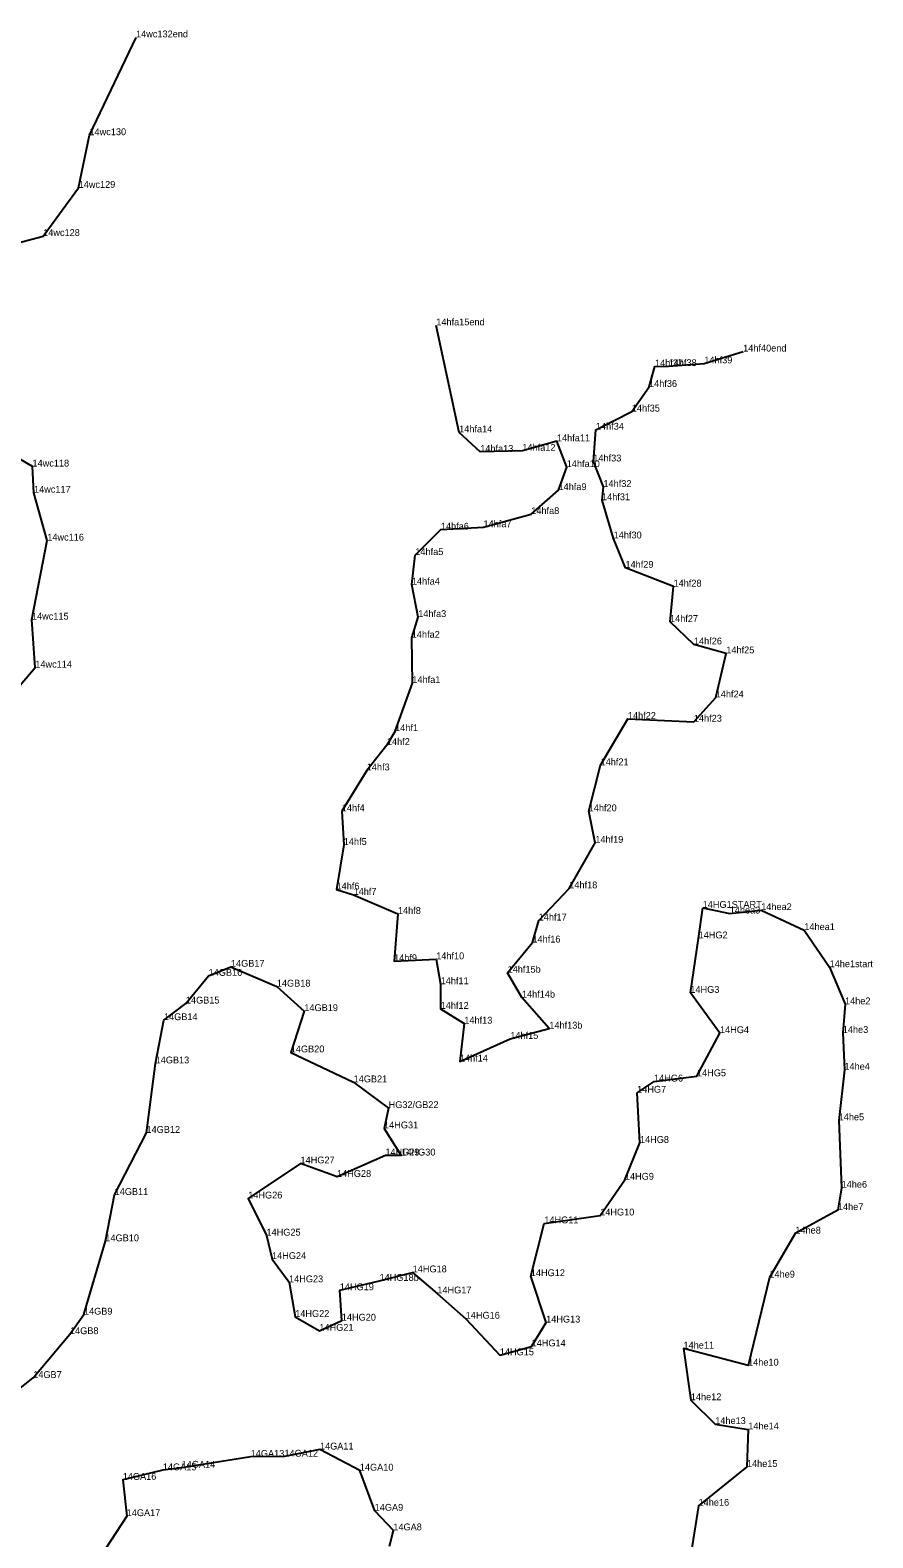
# Model space of a CAD drawing. Extents: x 2072529 to 2267990, y 436423 to 470008.
# Drawn here: x 2256512 to 2257127, y 441770 to 442872 of the extents above; entities that cross this region are included whole.
import ezdxf

# ---------------------------------------------------------------- set-up
doc = ezdxf.new("R2010")
doc.units = 0
doc.layers.add('Level 3', color=7, linetype='Continuous')
doc.layers.add('Old_Level_52', color=7, linetype='Continuous')

msp = doc.modelspace()

# ---------------------------------------------------------------- linework, layer by layer
at = {"layer": 'Level 3'}
for p, q in [((2256588.861, 442866.33), (2256588.861, 442866.33)), ((2256554.839, 442794.87), (2256554.839, 442794.87)), ((2256546.961, 442756.391), (2256546.961, 442756.391)), ((2256521.047, 442721.188), (2256521.047, 442721.188)), ((2256808.072, 442655.895), (2256808.072, 442655.895)), ((2257032.164, 442636.791), (2257032.164, 442636.791)), ((2256967.768, 442625.957), (2256967.768, 442625.957)), ((2256977.718, 442626.158), (2256977.718, 442626.158)), ((2257003.79, 442628.145), (2257003.79, 442628.145)), ((2256963.408, 442610.898), (2256963.408, 442610.898)), ((2256950.871, 442592.936), (2256950.871, 442592.936)), ((2256924.614, 442579.689), (2256924.614, 442579.689)), ((2256824.774, 442577.743), (2256824.774, 442577.743)), ((2256896.18, 442571.22), (2256896.18, 442571.22)), ((2256840.149, 442563.48), (2256840.149, 442563.48)), ((2256870.943, 442564.249), (2256870.943, 442564.249)), ((2256922.747, 442556.483), (2256922.747, 442556.483)), ((2256513.243, 442552.763), (2256513.243, 442552.763)), ((2256903.329, 442552.366), (2256903.329, 442552.366)), ((2256897.343, 442535.552), (2256897.343, 442535.552)), ((2256930.128, 442537.824), (2256930.128, 442537.824)), ((2256514.351, 442533.633), (2256514.351, 442533.633)), ((2256929.089, 442528.143), (2256929.089, 442528.143)), ((2256877.431, 442518.043), (2256877.431, 442518.043)), ((2256811.443, 442506.657), (2256811.443, 442506.657)), ((2256842.568, 442508.441), (2256842.568, 442508.441)), ((2256524.048, 442498.667), (2256524.048, 442498.667)), ((2256937.584, 442500.25), (2256937.584, 442500.25)), ((2256792.765, 442488.079), (2256792.765, 442488.079)), ((2256946.219, 442478.778), (2256946.219, 442478.778)), ((2256790.248, 442466.484), (2256790.248, 442466.484)), ((2256981.308, 442465.031), (2256981.308, 442465.031)), ((2256512.841, 442440.902), (2256512.841, 442440.902)), ((2256794.901, 442442.777), (2256794.901, 442442.777)), ((2256978.733, 442439.22), (2256978.733, 442439.22)), ((2256790.185, 442427.622), (2256790.185, 442427.622)), ((2256996.178, 442422.789), (2256996.178, 442422.789)), ((2257019.843, 442416.274), (2257019.843, 442416.274)), ((2256515.322, 442405.862), (2256515.322, 442405.862)), ((2256790.622, 442394.6), (2256790.622, 442394.6)), ((2257012.095, 442384.028), (2257012.095, 442384.028)), ((2256778.024, 442359.444), (2256778.024, 442359.444)), ((2256947.98, 442368.36), (2256947.98, 442368.36)), ((2256996.142, 442366.341), (2256996.142, 442366.341)), ((2256772.008, 442349.301), (2256772.008, 442349.301)), ((2256757.327, 442330.735), (2256757.327, 442330.735)), ((2256928.051, 442334.516), (2256928.051, 442334.516)), ((2256739.105, 442300.891), (2256739.105, 442300.891)), ((2256919.352, 442300.888), (2256919.352, 442300.888)), ((2256740.524, 442276.298), (2256740.524, 442276.298)), ((2256924.197, 442277.869), (2256924.197, 442277.869)), ((2256735.261, 442243.745), (2256735.261, 442243.745)), ((2256747.704, 442239.841), (2256747.704, 442239.841)), ((2256905.181, 442244.57), (2256905.181, 442244.57)), ((2256780.07, 442225.88), (2256780.07, 442225.88)), ((2257002.603, 442230.336), (2257002.603, 442230.336)), ((2257022.343, 442226.219), (2257022.343, 442226.219)), ((2257045.316, 442228.688), (2257045.316, 442228.688)), ((2256882.843, 442221.092), (2256882.843, 442221.092)), ((2256878.273, 442205), (2256878.273, 442205)), ((2256999.626, 442208.027), (2256999.626, 442208.027)), ((2257076.791, 442214.063), (2257076.791, 442214.063)), ((2256808.014, 442192.769), (2256808.014, 442192.769)), ((2256658.15, 442187.299), (2256658.15, 442187.299)), ((2256777.268, 442191.342), (2256777.268, 442191.342)), ((2256860.153, 442182.951), (2256860.153, 442182.951)), ((2257095.268, 442186.95), (2257095.268, 442186.95)), ((2256641.846, 442180.672), (2256641.846, 442180.672)), ((2256691.652, 442172.807), (2256691.652, 442172.807)), ((2256811.25, 442174.563), (2256811.25, 442174.563)), ((2256625.255, 442160.408), (2256625.255, 442160.408)), ((2256870.613, 442164.726), (2256870.613, 442164.726)), ((2256993.598, 442168.239), (2256993.598, 442168.239)), ((2257106.498, 442159.852), (2257106.498, 442159.852)), ((2256711.722, 442154.914), (2256711.722, 442154.914)), ((2256811.254, 442156.555), (2256811.254, 442156.555)), ((2256609.256, 442148.287), (2256609.256, 442148.287)), ((2256828.537, 442145.732), (2256828.537, 442145.732)), ((2256890.612, 442142.069), (2256890.612, 442142.069)), ((2257015.216, 442138.82), (2257015.216, 442138.82)), ((2257104.886, 442138.965), (2257104.886, 442138.965)), ((2256862.129, 442134.591), (2256862.129, 442134.591)), ((2256603.163, 442116.704), (2256603.163, 442116.704)), ((2256701.831, 442124.753), (2256701.831, 442124.753)), ((2256825.326, 442118.046), (2256825.326, 442118.046)), ((2256998.412, 442107.303), (2256998.412, 442107.303)), ((2257106.071, 442112.024), (2257106.071, 442112.024)), ((2256747.7, 442102.866), (2256747.7, 442102.866)), ((2256954.737, 442095.278), (2256954.737, 442095.278)), ((2256967.057, 442103.445), (2256967.057, 442103.445)), ((2256773.27, 442084.037), (2256773.27, 442084.037)), ((2257101.891, 442075.091), (2257101.891, 442075.091)), ((2256596.481, 442065.935), (2256596.481, 442065.935)), ((2256769.933, 442069.212), (2256769.933, 442069.212)), ((2256956.773, 442058.592), (2256956.773, 442058.592)), ((2256708.948, 442043.636), (2256708.948, 442043.636)), ((2256770.931, 442049.474), (2256770.931, 442049.474)), ((2256782.535, 442049.383), (2256782.535, 442049.383)), ((2256735.603, 442033.763), (2256735.603, 442033.763)), ((2256945.787, 442031.698), (2256945.787, 442031.698)), ((2256573.197, 442020.555), (2256573.197, 442020.555)), ((2256670.785, 442017.999), (2256670.785, 442017.999)), ((2257103.998, 442025.846), (2257103.998, 442025.846)), ((2256927.77, 442005.578), (2256927.77, 442005.578)), ((2257101.305, 442009.514), (2257101.305, 442009.514)), ((2256886.966, 441999.838), (2256886.966, 441999.838)), ((2256566.463, 441986.742), (2256566.463, 441986.742)), ((2256684.098, 441990.857), (2256684.098, 441990.857)), ((2257070.234, 441992.338), (2257070.234, 441992.338)), ((2256688.147, 441973.748), (2256688.147, 441973.748)), ((2256790.82, 441964.029), (2256790.82, 441964.029)), ((2256700.578, 441956.769), (2256700.578, 441956.769)), ((2256737.593, 441950.967), (2256737.593, 441950.967)), ((2256766.648, 441957.788), (2256766.648, 441957.788)), ((2256877.1, 441961.24), (2256877.1, 441961.24)), ((2257051.284, 441960.175), (2257051.284, 441960.175)), ((2256808.839, 441948.627), (2256808.839, 441948.627)), ((2256550.815, 441933.129), (2256550.815, 441933.129)), ((2256705.081, 441931.45), (2256705.081, 441931.45)), ((2256739.1, 441928.741), (2256739.1, 441928.741)), ((2256829.569, 441930.176), (2256829.569, 441930.176)), ((2256540.62, 441918.878), (2256540.62, 441918.878)), ((2256722.719, 441921.327), (2256722.719, 441921.327)), ((2256888.3, 441927.371), (2256888.3, 441927.371)), ((2256877.67, 441909.935), (2256877.67, 441909.935)), ((2256988.599, 441908.325), (2256988.599, 441908.325)), ((2256854.465, 441903.45), (2256854.465, 441903.45)), ((2257035.742, 441895.855), (2257035.742, 441895.855)), ((2256513.79, 441886.845), (2256513.79, 441886.845)), ((2256993.928, 441870.603), (2256993.928, 441870.603)), ((2257011.741, 441853.201), (2257011.741, 441853.201)), ((2257035.888, 441849.273), (2257035.888, 441849.273)), ((2256697.223, 441829.394), (2256697.223, 441829.394)), ((2256723.145, 441834.558), (2256723.145, 441834.558)), ((2256608.424, 441819.406), (2256608.424, 441819.406)), ((2256622.183, 441821.287), (2256622.183, 441821.287)), ((2256672.568, 441829.223), (2256672.568, 441829.223)), ((2256752.267, 441819.163), (2256752.267, 441819.163)), ((2257034.912, 441821.818), (2257034.912, 441821.818)), ((2256579.138, 441812.428), (2256579.138, 441812.428)), ((2256582.031, 441785.909), (2256582.031, 441785.909)), ((2256763.096, 441789.861), (2256763.096, 441789.861)), ((2256999.573, 441793.49), (2256999.573, 441793.49)), ((2256776.718, 441775.529), (2256776.718, 441775.529))]:
    msp.add_line(p, q, dxfattribs=at)
at = {"layer": 'Old_Level_52'}
for points in [[(2256524.048, 442498.667), (2256514.351, 442533.633), (2256513.243, 442552.763), (2256483.83, 442569.775), (2256449.942, 442547.661), (2256423.695, 442561.134), (2256411.887, 442599.94), (2256402.361, 442626.184), (2256403.543, 442645.218), (2256422.088, 442677.722), (2256449.372, 442701.938), (2256477.101, 442709.298), (2256521.047, 442721.188), (2256546.961, 442756.391), (2256554.839, 442794.87), (2256588.861, 442866.33)], [(2256778.024, 442359.444), (2256790.622, 442394.6), (2256790.185, 442427.622), (2256794.901, 442442.777), (2256790.248, 442466.484), (2256792.765, 442488.079), (2256811.443, 442506.657), (2256842.568, 442508.441), (2256877.431, 442518.043), (2256897.343, 442535.552), (2256903.329, 442552.366), (2256896.18, 442571.22), (2256870.943, 442564.249), (2256840.149, 442563.48), (2256824.774, 442577.743), (2256808.072, 442655.895)], [(2256978.733, 442439.22), (2256981.308, 442465.031), (2256946.219, 442478.778), (2256937.584, 442500.25), (2256929.089, 442528.143), (2256930.128, 442537.824), (2256922.747, 442556.483), (2256924.614, 442579.689), (2256950.871, 442592.936), (2256963.408, 442610.898), (2256967.768, 442625.957), (2256977.718, 442626.158), (2257003.79, 442628.145), (2257032.164, 442636.791)], [(2256471.058, 442354.313), (2256515.322, 442405.862), (2256512.841, 442440.902), (2256524.048, 442498.667)], [(2256778.024, 442359.444), (2256772.008, 442349.301), (2256757.327, 442330.735), (2256739.105, 442300.891), (2256740.524, 442276.298), (2256735.261, 442243.745), (2256747.704, 442239.841), (2256780.07, 442225.88), (2256777.268, 442191.342), (2256808.014, 442192.769), (2256811.25, 442174.563), (2256811.254, 442156.555), (2256828.537, 442145.732), (2256825.326, 442118.046), (2256862.129, 442134.591), (2256890.612, 442142.069), (2256870.613, 442164.726), (2256860.153, 442182.951), (2256878.273, 442205), (2256882.843, 442221.092), (2256905.181, 442244.57), (2256924.197, 442277.869), (2256919.352, 442300.888), (2256928.051, 442334.516), (2256947.98, 442368.36), (2256996.142, 442366.341), (2257012.095, 442384.028), (2257019.843, 442416.274), (2256996.178, 442422.789), (2256978.733, 442439.22)], [(2256474.479, 441855.925), (2256513.79, 441886.845), (2256540.62, 441918.878), (2256550.815, 441933.129), (2256566.463, 441986.742), (2256573.197, 442020.555), (2256596.481, 442065.935), (2256603.163, 442116.704), (2256609.256, 442148.287), (2256625.255, 442160.408), (2256641.846, 442180.672), (2256658.15, 442187.299), (2256691.652, 442172.807), (2256711.722, 442154.914), (2256701.831, 442124.753), (2256747.7, 442102.866), (2256773.27, 442084.037), (2256769.933, 442069.212), (2256782.535, 442049.383), (2256770.931, 442049.474), (2256735.603, 442033.763), (2256708.948, 442043.636), (2256670.785, 442017.999), (2256684.098, 441990.857), (2256688.147, 441973.748), (2256700.578, 441956.769), (2256705.081, 441931.45), (2256722.719, 441921.327), (2256739.1, 441928.741), (2256737.593, 441950.967), (2256766.648, 441957.788), (2256790.82, 441964.029), (2256808.839, 441948.627), (2256829.569, 441930.176), (2256854.465, 441903.45), (2256877.67, 441909.935), (2256888.3, 441927.371), (2256877.1, 441961.24), (2256886.966, 441999.838), (2256927.77, 442005.578), (2256945.787, 442031.698), (2256956.773, 442058.592), (2256954.737, 442095.278), (2256967.057, 442103.445), (2256998.412, 442107.303), (2257015.216, 442138.82), (2256993.598, 442168.239), (2256999.626, 442208.027), (2257002.603, 442230.336)], [(2257002.603, 442230.336), (2257022.343, 442226.219), (2257045.316, 442228.688), (2257076.791, 442214.063), (2257095.268, 442186.95)], [(2257095.268, 442186.95), (2257106.498, 442159.852), (2257104.886, 442138.965), (2257106.071, 442112.024), (2257101.891, 442075.091), (2257103.998, 442025.846), (2257101.305, 442009.514), (2257070.234, 441992.338), (2257051.284, 441960.175), (2257035.742, 441895.855), (2256988.599, 441908.325), (2256993.928, 441870.603), (2257011.741, 441853.201), (2257035.888, 441849.273), (2257034.912, 441821.818), (2256999.573, 441793.49), (2256993.448, 441755.079)], [(2256773.834, 441764.094), (2256776.718, 441775.529), (2256763.096, 441789.861), (2256752.267, 441819.163), (2256723.145, 441834.558), (2256697.223, 441829.394), (2256672.568, 441829.223), (2256622.183, 441821.287), (2256608.424, 441819.406), (2256579.138, 441812.428), (2256582.031, 441785.909), (2256566.509, 441761.957)]]:
    msp.add_lwpolyline(points, dxfattribs=at)

# ---------------------------------------------------------------- texts
for s, p in [('14wc132end', (2256588.861, 442866.33)), ('14wc130', (2256554.839, 442794.87)), ('14wc129', (2256546.961, 442756.391)), ('14wc128', (2256521.047, 442721.188)), ('14hfa15end', (2256808.072, 442655.895)), ('14hf39', (2257003.79, 442628.145)), ('14hf40end', (2257032.164, 442636.791)), ('14hf37', (2256967.768, 442625.957)), ('14hf38', (2256977.718, 442626.158)), ('14hf36', (2256963.408, 442610.898)), ('14hf35', (2256950.871, 442592.936)), ('14hfa14', (2256824.774, 442577.743)), ('14hf34', (2256924.614, 442579.689)), ('14hfa13', (2256840.149, 442563.48)), ('14hfa12', (2256870.943, 442564.249)), ('14hfa11', (2256896.18, 442571.22)), ('14wc118', (2256513.243, 442552.763)), ('14hfa10', (2256903.329, 442552.366)), ('14hf33', (2256922.747, 442556.483)), ('14wc117', (2256514.351, 442533.633)), ('14hfa9', (2256897.343, 442535.552)), ('14hf32', (2256930.128, 442537.824)), ('14hfa8', (2256877.431, 442518.043)), ('14hf31', (2256929.089, 442528.143)), ('14hfa7', (2256842.568, 442508.441)), ('14wc116', (2256524.048, 442498.667)), ('14hfa6', (2256811.443, 442506.657)), ('14hf30', (2256937.584, 442500.25)), ('14hfa5', (2256792.765, 442488.079)), ('14hf29', (2256946.219, 442478.778)), ('14hfa4', (2256790.248, 442466.484)), ('14hf28', (2256981.308, 442465.031)), ('14hfa3', (2256794.901, 442442.777)), ('14wc115', (2256512.841, 442440.902)), ('14hf27', (2256978.733, 442439.22)), ('14hfa2', (2256790.185, 442427.622)), ('14hf26', (2256996.178, 442422.789)), ('14hf25', (2257019.843, 442416.274)), ('14wc114', (2256515.322, 442405.862)), ('14hfa1', (2256790.622, 442394.6)), ('14hf24', (2257012.095, 442384.028)), ('14hf22', (2256947.98, 442368.36)), ('14hf23', (2256996.142, 442366.341)), ('14hf1', (2256778.024, 442359.444)), ('14hf2', (2256772.008, 442349.301)), ('14hf3', (2256757.327, 442330.735)), ('14hf21', (2256928.051, 442334.516)), ('14hf4', (2256739.105, 442300.891)), ('14hf20', (2256919.352, 442300.888)), ('14hf5', (2256740.524, 442276.298)), ('14hf19', (2256924.197, 442277.869)), ('14hf6', (2256735.261, 442243.745)), ('14hf18', (2256905.181, 442244.57)), ('14hf7', (2256747.704, 442239.841)), ('14hf8', (2256780.07, 442225.88)), ('14hf17', (2256882.843, 442221.092)), ('14HG1START', (2257002.603, 442230.336)), ('14hea3', (2257022.343, 442226.219)), ('14hea2', (2257045.316, 442228.688)), ('14hea1', (2257076.791, 442214.063)), ('14hf16', (2256878.273, 442205)), ('14HG2', (2256999.626, 442208.027)), ('14hf9', (2256777.268, 442191.342)), ('14hf10', (2256808.014, 442192.769)), ('14GB16', (2256641.846, 442180.672)), ('14GB17', (2256658.15, 442187.299)), ('14hf15b', (2256860.153, 442182.951)), ('14he1start', (2257095.268, 442186.95)), ('14GB18', (2256691.652, 442172.807)), ('14hf11', (2256811.25, 442174.563)), ('14HG3', (2256993.598, 442168.239)), ('14GB15', (2256625.255, 442160.408)), ('14GB19', (2256711.722, 442154.914)), ('14hf12', (2256811.254, 442156.555)), ('14hf14b', (2256870.613, 442164.726)), ('14he2', (2257106.498, 442159.852)), ('14GB14', (2256609.256, 442148.287)), ('14hf13', (2256828.537, 442145.732)), ('14hf15', (2256862.129, 442134.591)), ('14hf13b', (2256890.612, 442142.069)), ('14HG4', (2257015.216, 442138.82)), ('14he3', (2257104.886, 442138.965)), ('14GB20', (2256701.831, 442124.753)), ('14GB13', (2256603.163, 442116.704)), ('14hf14', (2256825.326, 442118.046)), ('14he4', (2257106.071, 442112.024)), ('14GB21', (2256747.7, 442102.866)), ('14HG6', (2256967.057, 442103.445)), ('14HG5', (2256998.412, 442107.303)), ('14HG7', (2256954.737, 442095.278)), ('HG32/GB22', (2256773.27, 442084.037)), ('14HG31', (2256769.933, 442069.212)), ('14he5', (2257101.891, 442075.091)), ('14GB12', (2256596.481, 442065.935)), ('14HG8', (2256956.773, 442058.592)), ('14HG29', (2256770.931, 442049.474)), ('14HG30', (2256782.535, 442049.383)), ('14HG27', (2256708.948, 442043.636)), ('14HG28', (2256735.603, 442033.763)), ('14HG9', (2256945.787, 442031.698)), ('14he6', (2257103.998, 442025.846)), ('14GB11', (2256573.197, 442020.555)), ('14HG26', (2256670.785, 442017.999)), ('14HG10', (2256927.77, 442005.578)), ('14he7', (2257101.305, 442009.514)), ('14HG25', (2256684.098, 441990.857)), ('14HG11', (2256886.966, 441999.838)), ('14he8', (2257070.234, 441992.338)), ('14GB10', (2256566.463, 441986.742)), ('14HG24', (2256688.147, 441973.748)), ('14HG23', (2256700.578, 441956.769)), ('14HG18b', (2256766.648, 441957.788)), ('14HG18', (2256790.82, 441964.029)), ('14HG12', (2256877.1, 441961.24)), ('14he9', (2257051.284, 441960.175)), ('14HG19', (2256737.593, 441950.967)), ('14HG17', (2256808.839, 441948.627)), ('14GB9', (2256550.815, 441933.129)), ('14HG22', (2256705.081, 441931.45)), ('14HG20', (2256739.1, 441928.741)), ('14HG16', (2256829.569, 441930.176)), ('14HG13', (2256888.3, 441927.371)), ('14GB8', (2256540.62, 441918.878)), ('14HG21', (2256722.719, 441921.327)), ('14HG15', (2256854.465, 441903.45)), ('14HG14', (2256877.67, 441909.935)), ('14he11', (2256988.599, 441908.325)), ('14he10', (2257035.742, 441895.855)), ('14GB7', (2256513.79, 441886.845)), ('14he12', (2256993.928, 441870.603)), ('14he13', (2257011.741, 441853.201)), ('14he14', (2257035.888, 441849.273)), ('14GA13', (2256672.568, 441829.223)), ('14GA12', (2256697.223, 441829.394)), ('14GA11', (2256723.145, 441834.558)), ('14GA15', (2256608.424, 441819.406)), ('14GA14', (2256622.183, 441821.287)), ('14GA10', (2256752.267, 441819.163)), ('14he15', (2257034.912, 441821.818)), ('14GA16', (2256579.138, 441812.428)), ('14he16', (2256999.573, 441793.49)), ('14GA17', (2256582.031, 441785.909)), ('14GA9', (2256763.096, 441789.861)), ('14GA8', (2256776.718, 441775.529))]:
    msp.add_text(s, height=5).set_placement(p)

doc.saveas('drawing.dxf')
